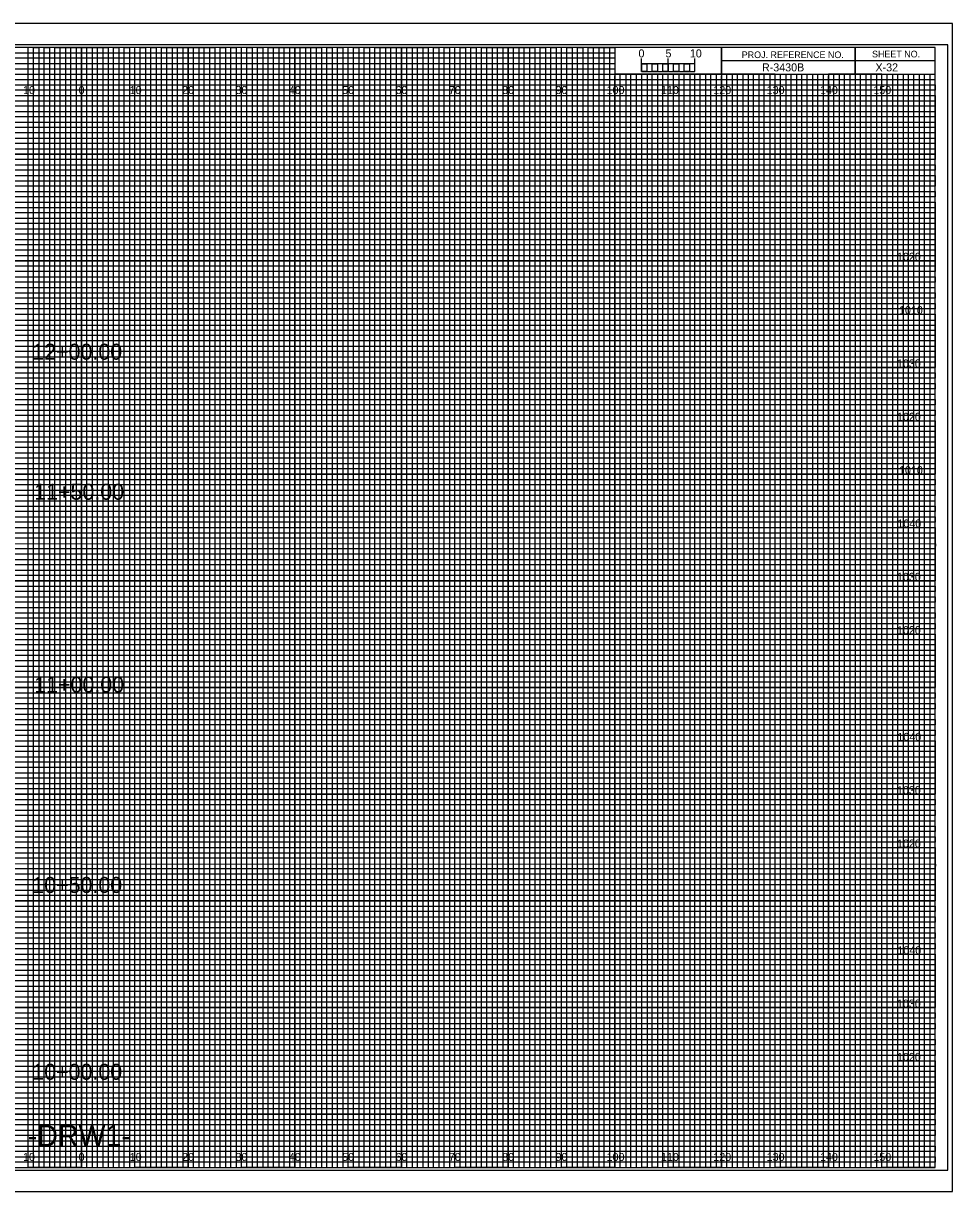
# Model space of a CAD drawing. Extents: x -13 to 323, y -5 to 215.
# Drawn here: x 149.1 to 323.3, y -4.5 to 214.5 of the extents above; entities that cross this region are included whole.
import ezdxf

# ---------------------------------------------------------------- set-up
doc = ezdxf.new("R2010")
doc.units = 0
for name, color, linetype in [('Exist Cross Section Cell', 7, 'Continuous'), ('Exist XS Ground Line', 7, 'Continuous'), ('Prop CMT Bridge Metal Rail', 7, 'Continuous'), ('Prop CMT Bridge Metal Rail Post', 7, 'Continuous'), ('Prop CMT Concrete Structures', 7, 'Continuous'), ('Prop CMT Guardrail Widen Shoulder', 7, 'Continuous'), ('Prop CMT Pvmt Course 1', 7, 'Continuous'), ('Prop CMT Pvmt Course 2', 7, 'Continuous'), ('Prop CMT Pvmt Course 3', 7, 'Continuous'), ('Prop CMT Pvmt Surface', 7, 'Continuous'), ('Prop CMT Pvmt Surface Shoulder', 7, 'Continuous'), ('Prop CMT Shld Paved Course 1', 7, 'Continuous'), ('Prop CMT Shld Paved Course 2', 7, 'Continuous'), ('Prop CMT Shld Paved Course 3', 7, 'Continuous'), ('Prop CMT Slope Grass', 7, 'Continuous'), ('Prop CMT Subgrade Earthwork', 7, 'Continuous'), ('Scratch_Level_0', 7, 'Continuous')]:
    doc.layers.add(name, color=color, linetype=linetype)

msp = doc.modelspace()

# ---------------------------------------------------------------- linework, layer by layer
at = {"layer": 'Prop CMT Pvmt Course 2'}
for p, q in [((265, 205.49), (265, 207.9)), ((265, 206.9), (265, 207.9)), ((270, 205.49), (270, 207.9)), ((275, 205.49), (275, 207.9)), ((275, 206.9), (275, 207.9))]:
    msp.add_line(p, q, dxfattribs=at)
for points in [[(275, 206.9), (265, 206.9), (265, 205.49), (275, 205.49)], [(265, 206.9), (266, 206.9), (266, 205.49), (265, 205.49)], [(267, 206.9), (268, 206.9), (268, 205.49), (267, 205.49)], [(269, 206.9), (270, 206.9), (270, 205.49), (269, 205.49)], [(271, 206.9), (272, 206.9), (272, 205.49), (271, 205.49)], [(273, 206.9), (274, 206.9), (274, 205.49), (273, 205.49)]]:
    msp.add_lwpolyline(points, close=True, dxfattribs=at)
at = {"layer": 'Prop CMT Pvmt Course 3'}
msp.add_lwpolyline([(-13.4, -4.5), (323.3, -4.5), (323.3, 214.5), (-13.4, 214.5)], close=True, dxfattribs=at)
at = {"layer": 'Prop CMT Pvmt Surface'}
for p, q in [((150, 0), (150, 210)), ((160, 0), (160, 210)), ((170, 0), (170, 210)), ((180, 0), (180, 210)), ((190, 0), (190, 210)), ((200, 0), (200, 210)), ((210, 0), (210, 210)), ((220, 0), (220, 210)), ((230, 0), (230, 210)), ((240, 0), (240, 210)), ((250, 0), (250, 210)), ((260, 0), (260, 204.69)), ((270, 0), (270, 204.69)), ((280, 0), (280, 204.69)), ((290, 0), (290, 204.69)), ((300, 0), (300, 204.69)), ((310, 0), (310, 204.69)), ((0, 200), (320, 200)), ((0, 190), (320, 190)), ((0, 180), (320, 180)), ((0, 170), (320, 170)), ((0, 160), (320, 160)), ((0, 150), (320, 150)), ((0, 140), (320, 140)), ((0, 130), (320, 130)), ((0, 120), (320, 120)), ((0, 110), (320, 110)), ((0, 100), (320, 100)), ((0, 90), (320, 90)), ((0, 80), (320, 80)), ((0, 70), (320, 70)), ((0, 60), (320, 60)), ((0, 50), (320, 50)), ((0, 40), (320, 40)), ((0, 30), (320, 30)), ((0, 20), (320, 20)), ((0, 10), (320, 10))]:
    msp.add_line(p, q, dxfattribs=at)
at = {"layer": 'Prop CMT Pvmt Surface Shoulder'}
for p, q in [((323.3, 214.5), (-13.4, 214.5)), ((-13.4, -4.5), (323.3, -4.5))]:
    msp.add_line(p, q, dxfattribs=at)
at = {"layer": 'Prop CMT Shld Paved Course 1'}
for p, q in [((0, 209), (260, 209)), ((260, 209), (260, 207.98)), ((260, 207.98), (0, 207.98)), ((0, 207), (260, 207)), ((260, 205.89), (0, 205.89)), ((260, 207), (260, 205.89)), ((0, 204), (320, 204))]:
    msp.add_line(p, q, dxfattribs=at)
for points in [[(0, 203), (270, 203), (320, 203), (320, 202), (0, 202)], [(0, 201), (320, 201), (320, 199), (0, 199)], [(0, 198), (320, 198), (320, 197), (0, 196.98)], [(0, 196), (320, 196), (320, 194), (0, 194)], [(0, 193), (320, 193), (320, 192), (0, 192)], [(0, 191), (320, 191), (320, 189), (0, 189)], [(0, 188), (320, 188), (320, 187), (0, 187)], [(0, 186), (320, 186), (320, 184), (0, 184)], [(0, 183), (320, 183), (320, 182), (0, 182)], [(0, 181), (320, 181), (320, 179), (0, 179)], [(0, 178), (320, 178), (320, 177), (0, 177)], [(0, 176), (320, 176), (320, 173.95), (320, 173), (320, 172), (0, 172)], [(0, 174), (320, 174), (320, 173), (0, 173)], [(0, 171), (320, 171), (320, 169), (0, 169.03)], [(0, 169.03), (320, 169), (320, 168), (0, 168)], [(0, 167), (320, 167), (320, 166), (0, 166)], [(0, 164), (320, 164), (320, 163), (0, 163)], [(0, 162), (320, 162), (320, 161), (0, 161)], [(-0.07, 158.89), (320, 158.89), (320, 157.88), (-0.07, 157.88)], [(0, 157), (320, 157), (320, 156), (0, 156)], [(0, 154), (320, 154), (320, 153), (0, 153)], [(0, 152), (320, 152), (320, 151), (0, 151)], [(0, 149), (320, 149), (320, 148), (0, 148)], [(0, 147), (320, 147), (320, 146), (0, 146)], [(0, 144), (320, 144), (320, 143), (0, 143)], [(0, 142), (320, 142), (320, 141), (0, 141)], [(0, 139), (320, 139), (319.99, 137.98), (0, 138)], [(0, 137), (320, 137), (320, 136), (0, 136)], [(0, 134), (320, 134), (320, 133), (0, 133)], [(0, 132), (320, 132), (320, 131), (0, 131)], [(0, 129), (320, 129), (320, 128), (0, 128)], [(0, 127), (320, 127), (320, 126), (0, 126)], [(0, 124), (320, 124), (320, 123), (0, 123)], [(0, 122), (320, 122), (320, 121), (0, 121)], [(0, 119), (320, 119), (320, 118), (0, 118)], [(0, 116.99), (320.07, 116.91), (320, 116), (0, 116)], [(0, 114), (320, 114), (320, 113), (0, 113)], [(0, 112), (320, 112), (320, 111), (0, 111)], [(0, 109), (320, 109), (320, 108), (0, 108)], [(0, 107), (320, 107), (320, 106), (0, 106)], [(0, 104), (320, 104), (320, 103), (0, 103)], [(0, 102), (320, 102), (320, 101), (0, 101)], [(0, 99), (320, 99), (320, 98), (0, 98)], [(0, 97), (320, 97), (320, 96), (0, 96)], [(0, 94), (320, 94), (320, 93), (0, 93)], [(0, 92), (320, 92), (320, 91), (0, 91)], [(0, 89), (320, 89), (320, 88), (0, 88)], [(0, 87), (320, 87), (320, 86), (0, 86)], [(0, 84), (320, 84), (320, 83), (0, 83)], [(0, 82), (320, 82), (320, 81), (0, 81)], [(0, 79), (320, 79), (319.99, 77.98), (0, 78)], [(0, 77), (320, 77), (320, 76), (0, 76)], [(0, 74), (320, 74), (320, 73), (0, 73)], [(0, 72), (320, 72), (320, 71), (0, 71)], [(0, 69), (320, 69), (320, 68), (0, 68)], [(0, 67), (320, 67), (320, 66), (0, 66)], [(0, 64), (320, 64), (320, 63), (0, 63)], [(0, 62), (320, 62), (320, 61), (0, 61)], [(0, 59), (320, 59), (320, 58), (0, 58)], [(0, 56.99), (320.07, 56.91), (320, 56), (0, 56)], [(0, 54), (320, 54), (320, 53), (0, 53)], [(0, 52), (320, 52), (320, 51), (0, 51)], [(0, 49), (320, 49), (320, 48), (0, 48)], [(0, 47), (320, 47), (320, 46), (0, 46)], [(0, 44), (320, 44), (320, 43), (0, 43)], [(0, 42), (320, 42), (320, 41), (0, 41)], [(0, 39), (320, 39), (320, 38), (0, 38)], [(0, 37), (320, 37), (320, 36), (0, 36)], [(0, 34), (320, 34), (320, 33), (0, 33)], [(0, 32), (320, 32), (320, 31), (0, 31)], [(0, 29), (320, 29), (320, 28), (0, 28)], [(0, 27), (320, 27), (320, 26), (0, 26)], [(0, 24), (320, 24), (320, 23), (0, 23)], [(0, 22), (320, 22), (320, 21), (0, 21)], [(0, 19), (320, 19), (320, 18), (0, 18)], [(0, 17), (320, 17), (320, 16), (0, 16)], [(0, 14), (320, 14), (320, 13), (0, 13)], [(0, 12), (320, 12), (320, 11), (0, 11)], [(0, 9), (320, 9), (320, 8), (0, 8)], [(0, 7), (320, 7), (320, 6), (0, 6)], [(0, 4), (320, 4), (320, 3), (0, 3)], [(0, 2), (320, 2), (320, 1), (0, 1)]]:
    msp.add_lwpolyline(points, dxfattribs=at)
at = {"layer": 'Prop CMT Shld Paved Course 2'}
for p, q in [((305, 210), (305, 205)), ((305, 205), (305, 210)), ((280, 207.5), (280, 205)), ((320, 207.49), (280, 207.49)), ((280, 205), (320, 205))]:
    msp.add_line(p, q, dxfattribs=at)
for points in [[(320, 210), (0, 210), (0, 0), (320, 0)], [(280, 210), (260, 210), (260, 205.03), (280, 205.03)], [(320, 210), (280, 210), (280, 205), (320, 205)]]:
    msp.add_lwpolyline(points, close=True, dxfattribs=at)
at = {"layer": 'Prop CMT Shld Paved Course 3'}
for p, q in [((267, 205), (266.01, 205)), ((266.01, 205), (266.01, 0)), ((267, 0), (267, 205)), ((269, 205), (268, 205)), ((268, 205), (268, 0)), ((269, 0), (269, 205)), ((266.01, 0), (265, 0)), ((268, 0), (267, 0))]:
    msp.add_line(p, q, dxfattribs=at)
for points in [[(150, 0), (151, 0), (151, 210), (152, 210), (152, 0)], [(152, 0), (153, 0), (153, 210), (154, 210), (154, 0)], [(155, 0), (156, 0), (156, 210), (157, 210), (157, 0)], [(157, 0), (158, 0), (158, 210), (159, 210), (159, 0)], [(160, 0), (161, 0), (161, 210), (162, 210), (162, 0)], [(162, 0), (163, 0), (163, 210), (164, 210), (164, 0)], [(165, 0), (166, 0), (166, 210), (167, 210), (167, 0)], [(167, 0), (168, 0), (168, 210), (169, 210), (169, 0)], [(170, 0), (171, 0), (171, 210), (172, 210), (172, 0)], [(172, 0), (173, 0), (173, 210), (174, 210), (174, 0)], [(175, 0), (176, 0), (176, 210), (177, 210), (177, 0)], [(177, 0), (178, 0), (178, 210), (179, 210), (179, 0)], [(180, 0), (181, 0), (181, 210), (182, 210), (182, 0)], [(182, 0), (183, 0), (183, 210), (184, 210), (184, 0)], [(185, 0), (186, 0), (186, 210), (187, 210), (187, 0)], [(187, 0), (188, 0), (188, 210), (189, 210), (189, 0)], [(190, 0), (191, 0), (191, 210), (192, 210), (192, 0)], [(192, 0), (193, 0), (193, 210), (194, 210), (194, 0)], [(195, 0), (196, 0), (196, 210), (197, 210), (197, 0)], [(197, 0), (198, 0), (198, 210), (199, 210), (199, 0)], [(200, 0), (201, 0), (201, 210), (202, 210), (202, 0)], [(202, 0), (203, 0), (203, 210), (204, 210), (204, 0)], [(205, 0), (206, 0), (206, 210), (207, 210), (207, 0)], [(207, 0), (208, 0), (208, 210), (209, 210), (209, 0)], [(210, 0), (211, 0), (211, 210), (212, 210), (212, 0)], [(212, 0), (213, 0), (213, 210), (214, 210), (214, 0)], [(215, 0), (216, 0), (216, 210), (217, 210), (217, 0)], [(217, 0), (218, 0), (218, 210), (219, 210), (219, 0)], [(220, 0), (221, 0), (221, 210), (222, 210), (222, 0)], [(222, 0), (223, 0), (223, 210), (224, 210), (224, 0)], [(225, 0), (226, 0), (226, 210), (227, 210), (227, 0)], [(227, 0), (228, 0), (228, 210), (229, 210), (229, 0)], [(230, 0), (231, 0), (231, 210), (232, 210), (232, 0)], [(232, 0), (233, 0), (233, 210), (234, 210), (234, 0)], [(235, 0), (236, 0), (236, 210), (237, 210), (237, 0)], [(237, 0), (238, 0), (238, 210), (239, 210), (239, 0)], [(240, 0), (241, 0), (241, 210), (242, 210), (242, 0)], [(242, 0), (243, 0), (243, 210), (244, 210), (244, 0)], [(245, 0), (246, 0), (246, 210), (247, 210), (247, 0)], [(247, 0), (248, 0), (248, 210), (249, 210), (249, 0)], [(250, 0), (251, 0), (251, 210), (252, 210), (252, 0)], [(252, 0), (253, 0), (253, 210), (254, 210), (254, 0)], [(255, 0), (256, 0), (256, 210), (257, 210), (257, 0)], [(257, 0), (258, 0), (258, 210), (259, 210), (259, 0)], [(260, 0), (261, 0), (261, 205), (262.02, 205), (262.02, 0)], [(262, 0), (263, 0), (263, 205), (263.99, 205), (263.99, 0)], [(270, 0), (270.98, 0), (270.98, 205), (272, 205), (272, 0)], [(272, 0), (273, 0), (273, 205), (274.05, 205), (274.05, 0)], [(275, 0), (276, 0), (276, 205), (277, 205), (277, 0)], [(277, 0), (278, 0), (278, 205), (279, 205), (279, 0)], [(280, 0), (281, 0), (281, 205), (282, 205), (282, 0)], [(282, 0), (283, 0), (283, 205), (284, 205), (284, 0)], [(285, 0), (286, 0), (286, 205), (287, 205), (287, 0)], [(287, 0), (288, 0), (288, 205), (289, 205), (289, 0)], [(290, 0), (291, 0), (291, 205), (292, 205), (292, 0)], [(292, 0), (293, 0), (293, 205), (294, 205), (294, 0)], [(295, 0), (296, 0), (296, 205), (297, 205), (297, 0)], [(297, 0), (298, 0), (298, 205), (299, 205), (299, 0)], [(300, 0), (301, 0), (301, 205), (302, 205), (302, 0)], [(302, 0), (303, 0), (303, 205), (304, 205), (304, 0)], [(305, 0), (306, 0), (306, 205), (307, 205), (307, 0)], [(307, 0), (308, 0), (308, 205), (309, 205), (309, 0)], [(310, 0), (311, 0), (311, 205), (312, 205), (312, 0)], [(312, 0), (313, 0), (313, 205), (314, 205), (314, 0)], [(315, 0), (316, 0), (316, 205), (317, 205), (317, 0)], [(317, 0), (318, 0), (318, 205), (319, 205), (319, 0)]]:
    msp.add_lwpolyline(points, dxfattribs=at)
at = {"layer": 'Prop CMT Slope Grass'}
for points in [[(145, 0), (155, 0), (155, 210), (165, 210), (165, 0), (175, 0), (175, 210), (185, 210), (185, 0), (195, 0), (195, 210), (205, 210), (205, 0), (215, 0), (215, 210), (225, 210), (225, 0), (235, 0), (235, 210), (245, 210), (245, 0), (255, 0), (255, 210), (259.93, 210), (260, 210), (260, 205), (264.99, 205), (264.99, 0), (275, 0), (275, 205), (285, 205), (285, 0), (295, 0), (295, 205), (305, 205), (305, 0), (315, 0), (315, 205)], [(0, 205), (275, 205)], [(0, 185), (320, 185), (320, 195), (0, 195)], [(0, 165), (320, 165), (320, 175), (0, 175)], [(0, 145), (320, 145), (320, 155), (0, 155)], [(0, 125), (320, 125), (320, 135), (0, 135)], [(0, 105), (320, 105), (320, 115), (0, 115)], [(0, 85), (320, 85), (320, 95), (0, 95)], [(0, 65), (320, 65), (320, 75), (0, 75)], [(0, 45), (320, 45), (320, 55), (0, 55)], [(0, 25), (320, 25), (320, 35), (0, 35)], [(0, 5), (320, 5), (320, 15), (0, 15)]]:
    msp.add_lwpolyline(points, dxfattribs=at)
at = {"layer": 'Prop CMT Subgrade Earthwork'}
msp.add_lwpolyline([(-10.8, -0.5), (322.4, -0.5), (322.4, 210.5), (-10.8, 210.5)], close=True, dxfattribs=at)
at = {"layer": 'Scratch_Level_0'}
for p, q in [((150, 210), (140, 210)), ((150, 0), (150, 210)), ((170, 210), (160, 210)), ((160, 210), (160, 0)), ((170, 0), (170, 210)), ((190, 210), (180, 210)), ((180, 210), (180, 0)), ((190, 0), (190, 210)), ((210, 210), (200, 210)), ((200, 210), (200, 0)), ((210, 0), (210, 210)), ((230, 210), (220, 210)), ((220, 210), (220, 0)), ((230, 0), (230, 210)), ((250, 210), (240, 210)), ((240, 210), (240, 0)), ((250, 0), (250, 210)), ((260, 210), (260, 0)), ((270, 0), (270, 205)), ((290, 205), (280, 205)), ((280, 205), (280, 0)), ((290, 0), (290, 205)), ((310, 205), (300, 205)), ((300, 205), (300, 0)), ((310, 0), (310, 205)), ((160, 0), (150, 0)), ((180, 0), (170, 0)), ((200, 0), (190, 0)), ((220, 0), (210, 0)), ((240, 0), (230, 0)), ((260, 0), (250, 0)), ((280, 0), (270, 0)), ((300, 0), (290, 0)), ((320, 0), (310, 0)), ((320, 0), (320, 0))]:
    msp.add_line(p, q, dxfattribs=at)
for points in [[(0, 200), (320, 200), (320, 190), (0, 190)], [(0, 180), (320, 180), (320, 170), (0, 170)], [(0, 160), (320, 160), (320, 150), (0, 150)], [(0, 140), (320, 140), (320, 130), (0, 130)], [(0, 120), (320, 120), (320, 110), (0, 110)], [(0, 100), (320, 100), (320, 90), (0, 90)], [(0, 80), (320, 80), (320, 70), (0, 70)], [(0, 60), (320, 60), (320, 50), (0, 50)], [(0, 40), (320, 40), (320, 30), (0, 30)], [(0, 20), (320, 20), (320, 10), (0, 10)]]:
    msp.add_lwpolyline(points, dxfattribs=at)

# ---------------------------------------------------------------- texts
at = {"layer": 'Exist Cross Section Cell'}
for s, p in [('10', (149.04, 201.25)), ('0', (159.45, 201.25)), ('0', (159.45, 201.25)), ('10', (169.04, 201.25)), ('20', (178.86, 201.25)), ('30', (188.86, 201.25)), ('40', (198.86, 201.25)), ('50', (208.86, 201.25)), ('60', (218.86, 201.25)), ('70', (228.86, 201.25)), ('80', (238.86, 201.25)), ('90', (248.86, 201.25)), ('100', (258.44, 201.25)), ('110', (268.62, 201.25)), ('120', (278.44, 201.25)), ('130', (288.44, 201.25)), ('140', (298.44, 201.25)), ('150', (308.44, 201.25)), ('10', (149.04, 1.25)), ('0', (159.45, 1.25)), ('0', (159.45, 1.25)), ('10', (169.04, 1.25)), ('20', (178.86, 1.25)), ('30', (188.86, 1.25)), ('40', (198.86, 1.25)), ('50', (208.86, 1.25)), ('60', (218.86, 1.25)), ('70', (228.86, 1.25)), ('80', (238.86, 1.25)), ('90', (248.86, 1.25)), ('100', (258.44, 1.25)), ('110', (268.62, 1.25)), ('120', (278.44, 1.25)), ('130', (288.44, 1.25)), ('140', (298.44, 1.25)), ('150', (308.44, 1.25))]:
    msp.add_text(s, height=1.5, dxfattribs=at).set_placement(p)
at = {"layer": 'Exist XS Ground Line'}
for s, p in [('12+00.00', (150.77, 151.45)), ('11+50.00', (151.13, 125.2)), ('11+00.00', (151.13, 89.05)), ('10+50.00', (150.77, 51.49)), ('10+00.00', (150.77, 16.47))]:
    msp.add_text(s, height=3, dxfattribs=at).set_placement(p)
at = {"layer": 'Prop CMT Bridge Metal Rail'}
msp.add_text('R-3430B', height=1.5, dxfattribs=at).set_placement((287.56, 205.5))
at = {"layer": 'Prop CMT Bridge Metal Rail Post'}
for s, p in [('5', (269.47, 208.12)), ('10', (274.04, 208.12))]:
    msp.add_text(s, height=1.5, dxfattribs=at).set_placement(p)
at = {"layer": 'Prop CMT Concrete Structures'}
msp.add_text('-DRW1-', height=4, dxfattribs=at).set_placement((149.93, 4))
at = {"layer": 'Prop CMT Guardrail Widen Shoulder'}
msp.add_text('X-32', height=1.5, dxfattribs=at).set_placement((308.83, 205.5))
at = {"layer": 'Prop CMT Pvmt Course 1'}
for s, p in [('1020', (312.87, 170)), ('1010', (313.25, 160)), ('1030', (312.86, 150)), ('1020', (312.87, 140)), ('1010', (313.25, 130)), ('1040', (312.95, 120)), ('1030', (312.86, 110)), ('1020', (312.87, 100)), ('1040', (312.95, 80)), ('1030', (312.86, 70)), ('1020', (312.87, 60)), ('1040', (312.95, 40)), ('1030', (312.86, 30)), ('1020', (312.87, 20))]:
    msp.add_text(s, height=1.5, dxfattribs=at).set_placement(p)
at = {"layer": 'Prop CMT Pvmt Course 2'}
msp.add_text('0', height=1.5, dxfattribs=at).set_placement((264.41, 208.12))
at = {"layer": 'Prop CMT Shld Paved Course 2'}
for s, p in [('PROJ. REFERENCE NO.', (283.77, 207.99)), ('SHEET NO.', (308.19, 208.12))]:
    msp.add_text(s, height=1.25, dxfattribs=at).set_placement(p)

doc.saveas('drawing.dxf')
